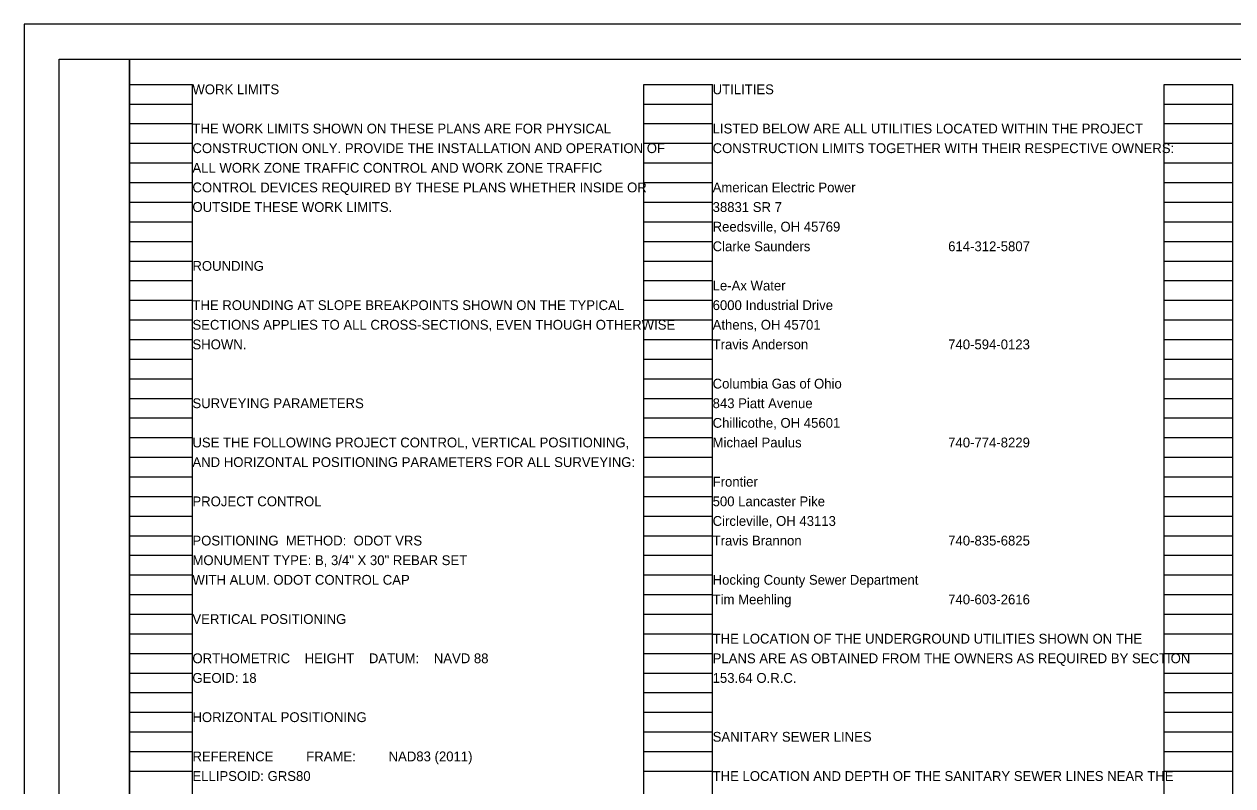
# Model space of a CAD drawing. Extents: x 0 to 34, y 0 to 22.
# Drawn here: x 0 to 17.24, y 11.13 to 22 of the extents above; entities that cross this region are included whole.
import ezdxf

# ---------------------------------------------------------------- set-up
doc = ezdxf.new("R2010")
doc.units = 0
for name, color, linetype in [('SH_Border', 7, 'Continuous'), ('SH_Cut_Line', 7, 'Continuous'), ('SH_Data', 7, 'Continuous'), ('SH_Text', 7, 'Continuous'), ('SV_X_Text', 7, 'Continuous')]:
    doc.layers.add(name, color=color, linetype=linetype)

msp = doc.modelspace()

# ---------------------------------------------------------------- linework, layer by layer
at = {"layer": 'SH_Border'}
for points in [[(0.5, 21.5), (1.5, 21.5), (1.5, 0.5), (0.5, 0.5)], [(1.5, 21.5), (33.5, 21.5), (33.5, 0.5), (1.5, 0.5)]]:
    msp.add_lwpolyline(points, close=True, dxfattribs=at)
at = {"layer": 'SH_Cut_Line'}
msp.add_lwpolyline([(0, 0), (34, 0), (34, 22), (0, 22)], close=True, dxfattribs=at)
at = {"layer": 'SH_Data'}
for p, q in [((1.5, 0.98), (1.5, 21.14)), ((1.5, 21.14), (2.4, 21.14)), ((2.4, 0.98), (2.4, 21.14)), ((8.84, 0.98), (8.84, 21.14)), ((8.84, 21.14), (9.82, 21.14)), ((9.82, 0.98), (9.82, 21.14)), ((16.26, 0.98), (16.26, 21.14)), ((16.26, 21.14), (17.24, 21.14)), ((17.24, 0.98), (17.24, 21.14)), ((1.5, 20.86), (2.4, 20.86)), ((8.84, 20.86), (9.82, 20.86)), ((16.26, 20.86), (17.24, 20.86)), ((1.5, 20.58), (2.4, 20.58)), ((8.84, 20.58), (9.82, 20.58)), ((16.26, 20.58), (17.24, 20.58)), ((1.5, 20.3), (2.4, 20.3)), ((8.84, 20.3), (9.82, 20.3)), ((16.26, 20.3), (17.24, 20.3)), ((1.5, 20.02), (2.4, 20.02)), ((8.84, 20.02), (9.82, 20.02)), ((16.26, 20.02), (17.24, 20.02)), ((1.5, 19.74), (2.4, 19.74)), ((8.84, 19.74), (9.82, 19.74)), ((16.26, 19.74), (17.24, 19.74)), ((1.5, 19.46), (2.4, 19.46)), ((8.84, 19.46), (9.82, 19.46)), ((16.26, 19.46), (17.24, 19.46)), ((1.5, 19.18), (2.4, 19.18)), ((8.84, 19.18), (9.82, 19.18)), ((16.26, 19.18), (17.24, 19.18)), ((1.5, 18.9), (2.4, 18.9)), ((8.84, 18.9), (9.82, 18.9)), ((16.26, 18.9), (17.24, 18.9)), ((1.5, 18.62), (2.4, 18.62)), ((8.84, 18.62), (9.82, 18.62)), ((16.26, 18.62), (17.24, 18.62)), ((1.5, 18.34), (2.4, 18.34)), ((8.84, 18.34), (9.82, 18.34)), ((16.26, 18.34), (17.24, 18.34)), ((1.5, 18.06), (2.4, 18.06)), ((8.84, 18.06), (9.82, 18.06)), ((16.26, 18.06), (17.24, 18.06)), ((1.5, 17.78), (2.4, 17.78)), ((8.84, 17.78), (9.82, 17.78)), ((16.26, 17.78), (17.24, 17.78)), ((1.5, 17.5), (2.4, 17.5)), ((8.84, 17.5), (9.82, 17.5)), ((16.26, 17.5), (17.24, 17.5)), ((1.5, 17.22), (2.4, 17.22)), ((8.84, 17.22), (9.82, 17.22)), ((16.26, 17.22), (17.24, 17.22)), ((1.5, 16.94), (2.4, 16.94)), ((8.84, 16.94), (9.82, 16.94)), ((16.26, 16.94), (17.24, 16.94)), ((1.5, 16.66), (2.4, 16.66)), ((8.84, 16.66), (9.82, 16.66)), ((16.26, 16.66), (17.24, 16.66)), ((1.5, 16.38), (2.4, 16.38)), ((8.84, 16.38), (9.82, 16.38)), ((16.26, 16.38), (17.24, 16.38)), ((1.5, 16.1), (2.4, 16.1)), ((8.84, 16.1), (9.82, 16.1)), ((16.26, 16.1), (17.24, 16.1)), ((1.5, 15.82), (2.4, 15.82)), ((8.84, 15.82), (9.82, 15.82)), ((16.26, 15.82), (17.24, 15.82)), ((1.5, 15.54), (2.4, 15.54)), ((8.84, 15.54), (9.82, 15.54)), ((16.26, 15.54), (17.24, 15.54)), ((1.5, 15.26), (2.4, 15.26)), ((8.84, 15.26), (9.82, 15.26)), ((16.26, 15.26), (17.24, 15.26)), ((1.5, 14.98), (2.4, 14.98)), ((8.84, 14.98), (9.82, 14.98)), ((16.26, 14.98), (17.24, 14.98)), ((1.5, 14.7), (2.4, 14.7)), ((8.84, 14.7), (9.82, 14.7)), ((16.26, 14.7), (17.24, 14.7)), ((1.5, 14.42), (2.4, 14.42)), ((8.84, 14.42), (9.82, 14.42)), ((16.26, 14.42), (17.24, 14.42)), ((1.5, 14.14), (2.4, 14.14)), ((8.84, 14.14), (9.82, 14.14)), ((16.26, 14.14), (17.24, 14.14)), ((1.5, 13.86), (2.4, 13.86)), ((8.84, 13.86), (9.82, 13.86)), ((16.26, 13.86), (17.24, 13.86)), ((1.5, 13.58), (2.4, 13.58)), ((8.84, 13.58), (9.82, 13.58)), ((16.26, 13.58), (17.24, 13.58)), ((1.5, 13.3), (2.4, 13.3)), ((8.84, 13.3), (9.82, 13.3)), ((16.26, 13.3), (17.24, 13.3)), ((1.5, 13.02), (2.4, 13.02)), ((8.84, 13.02), (9.82, 13.02)), ((16.26, 13.02), (17.24, 13.02)), ((1.5, 12.74), (2.4, 12.74)), ((8.84, 12.74), (9.82, 12.74)), ((16.26, 12.74), (17.24, 12.74)), ((1.5, 12.46), (2.4, 12.46)), ((8.84, 12.46), (9.82, 12.46)), ((16.26, 12.46), (17.24, 12.46)), ((1.5, 12.18), (2.4, 12.18)), ((8.84, 12.18), (9.82, 12.18)), ((16.26, 12.18), (17.24, 12.18)), ((1.5, 11.9), (2.4, 11.9)), ((8.84, 11.9), (9.82, 11.9)), ((16.26, 11.9), (17.24, 11.9)), ((1.5, 11.62), (2.4, 11.62)), ((8.84, 11.62), (9.82, 11.62)), ((16.26, 11.62), (17.24, 11.62)), ((1.5, 11.34), (2.4, 11.34)), ((8.84, 11.34), (9.82, 11.34)), ((16.26, 11.34), (17.24, 11.34))]:
    msp.add_line(p, q, dxfattribs=at)

# ---------------------------------------------------------------- texts
at = {"layer": 'SH_Text'}
for s, p in [('WORK LIMITS', (2.4, 21)), ('UTILITIES', (9.82, 21)), ('THE WORK LIMITS SHOWN ON THESE PLANS ARE FOR PHYSICAL ', (2.4, 20.44)), ('LISTED BELOW ARE ALL UTILITIES LOCATED WITHIN THE PROJECT ', (9.82, 20.44)), ('CONSTRUCTION ONLY. PROVIDE THE INSTALLATION AND OPERATION OF ', (2.4, 20.16)), ('CONSTRUCTION LIMITS TOGETHER WITH THEIR RESPECTIVE OWNERS:', (9.82, 20.16)), ('ALL WORK ZONE TRAFFIC CONTROL AND WORK ZONE TRAFFIC ', (2.4, 19.88)), ('CONTROL DEVICES REQUIRED BY THESE PLANS WHETHER INSIDE OR ', (2.4, 19.6)), ('American Electric Power', (9.82, 19.6)), ('OUTSIDE THESE WORK LIMITS.', (2.4, 19.32)), ('38831 SR 7', (9.82, 19.32)), ('Reedsville, OH 45769', (9.82, 19.04)), ('Clarke Saunders', (9.82, 18.76)), ('614-312-5807', (13.18, 18.76)), ('ROUNDING', (2.4, 18.48)), ('Le-Ax Water', (9.82, 18.2)), ('THE ROUNDING AT SLOPE BREAKPOINTS SHOWN ON THE TYPICAL ', (2.4, 17.92)), ('6000 Industrial Drive', (9.82, 17.92)), ('SECTIONS APPLIES TO ALL CROSS-SECTIONS, EVEN THOUGH OTHERWISE ', (2.4, 17.64)), ('Athens, OH 45701', (9.82, 17.64)), ('SHOWN.', (2.4, 17.36)), ('Travis Anderson', (9.82, 17.36)), ('740-594-0123', (13.18, 17.36)), ('Columbia Gas of Ohio ', (9.82, 16.8)), ('843 Piatt Avenue', (9.82, 16.52)), ('Chillicothe, OH 45601', (9.82, 16.24)), ('Michael Paulus', (9.82, 15.96)), ('740-774-8229', (13.18, 15.96)), ('Frontier', (9.82, 15.4)), ('500 Lancaster Pike', (9.82, 15.12)), ('Circleville, OH 43113', (9.82, 14.84)), ('Travis Brannon', (9.82, 14.56)), ('740-835-6825', (13.18, 14.56)), ('Hocking County Sewer Department', (9.82, 14)), ('Tim Meehling', (9.82, 13.72)), ('740-603-2616', (13.18, 13.72)), ('THE LOCATION OF THE UNDERGROUND UTILITIES SHOWN ON THE ', (9.82, 13.16)), ('PLANS ARE AS OBTAINED FROM THE OWNERS AS REQUIRED BY SECTION ', (9.82, 12.88)), ('153.64 O.R.C.', (9.82, 12.6)), ('SANITARY SEWER LINES', (9.82, 11.76)), ('THE LOCATION AND DEPTH OF THE SANITARY SEWER LINES NEAR THE ', (9.82, 11.2))]:
    msp.add_text(s, height=0.14, dxfattribs=at).set_placement(p)
at = {"layer": 'SV_X_Text'}
for s, p in [('SURVEYING PARAMETERS', (2.4, 16.52)), ('USE THE FOLLOWING PROJECT CONTROL, VERTICAL POSITIONING,', (2.4, 15.96)), ('AND HORIZONTAL POSITIONING PARAMETERS FOR ALL SURVEYING:', (2.4, 15.68)), ('PROJECT CONTROL', (2.4, 15.12)), ('POSITIONING  METHOD:  ODOT VRS', (2.4, 14.56)), ('MONUMENT TYPE: B, 3/4" X 30" REBAR SET', (2.4, 14.28)), ('WITH ALUM. ODOT CONTROL CAP', (2.4, 14)), ('VERTICAL POSITIONING', (2.4, 13.44)), ('ORTHOMETRIC    HEIGHT    DATUM:    NAVD 88', (2.4, 12.88)), ('GEOID: 18', (2.4, 12.6)), ('HORIZONTAL POSITIONING', (2.4, 12.04)), ('REFERENCE         FRAME:         NAD83 (2011)', (2.4, 11.48)), ('ELLIPSOID: GRS80', (2.4, 11.2))]:
    msp.add_text(s, height=0.14, dxfattribs=at).set_placement(p)

doc.saveas('drawing.dxf')
